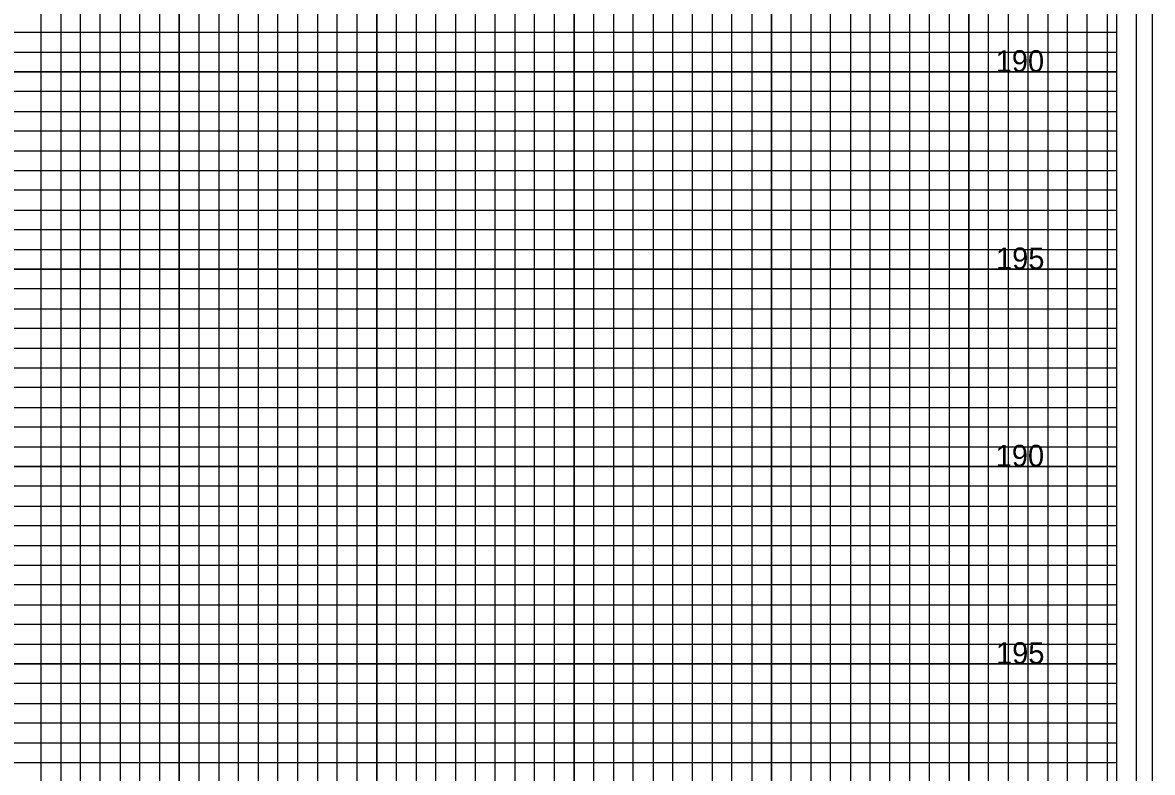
# Model space of a CAD drawing. Extents: x -4 to 103, y -2 to 67.
# Drawn here: x 74.78 to 103.4, y 32.25 to 51.25 of the extents above; entities that cross this region are included whole.
import ezdxf

# ---------------------------------------------------------------- set-up
doc = ezdxf.new("R2010")
doc.units = 0
for name, color, linetype in [('Exist XS Ground Line', 7, 'Continuous'), ('Old_Level_10', 7, 'Continuous'), ('Old_Level_5', 7, 'Continuous'), ('Old_Level_8', 7, 'Continuous'), ('Prop XS Dump Level', 7, 'Continuous'), ('Prop XS Finish Grade', 7, 'Continuous'), ('Prop XS Suitable Common Exc Shape', 7, 'Continuous')]:
    doc.layers.add(name, color=color, linetype=linetype)

msp = doc.modelspace()

# ---------------------------------------------------------------- linework, layer by layer
at = {"layer": 'Exist XS Ground Line'}
msp.add_lwpolyline([(103, 66), (-2.8, 66), (-2.8, -1), (103, -1)], close=True, dxfattribs=at)
at = {"layer": 'Old_Level_10'}
for p, q in [((91.25, 0), (91.25, 63.425)), ((93.75, 0), (93.75, 63.425)), ((96.25, 0), (96.25, 63.425)), ((98.75, 0), (98.75, 63.425)), ((101.25, 0), (101.25, 63.425)), ((76.25, 0), (76.25, 62)), ((78.75, 0), (78.75, 62)), ((81.25, 0), (81.25, 62)), ((83.75, 0), (83.75, 62)), ((86.25, 0), (86.25, 62)), ((88.75, 0), (88.75, 62)), ((0, 50), (102.5, 50)), ((0, 47.5), (102.5, 47.5)), ((0, 45), (102.5, 45)), ((0, 42.5), (102.5, 42.5)), ((0, 40), (102.5, 40)), ((0, 37.5), (102.5, 37.5)), ((0, 35), (102.5, 35)), ((0, 32.5), (102.5, 32.5))]:
    msp.add_line(p, q, dxfattribs=at)
at = {"layer": 'Old_Level_5'}
msp.add_lwpolyline([(103.4, 67.4), (-3.5, 67.4), (-3.5, -2.425), (103.4, -2.425)], close=True, dxfattribs=at)
at = {"layer": 'Old_Level_8'}
for points in [[(91.25, 0), (91.25, 63.425), (93.75, 63.425), (93.75, 0)], [(96.25, 0), (96.25, 63.425), (98.75, 63.425), (98.75, 0)], [(101.25, 0), (101.25, 63.425)], [(76.25, 0), (76.25, 62), (78.75, 62), (78.75, 0)], [(81.25, 0), (81.25, 62), (83.75, 62), (83.75, 0)], [(86.25, 0), (86.25, 62), (88.75, 62), (88.75, 0)], [(0, 47.5), (102.5, 47.5), (102.5, 50), (0, 50)], [(0, 42.5), (102.5, 42.5), (102.5, 45), (0, 45)], [(0, 37.5), (102.5, 37.5), (102.5, 40), (0, 40)], [(0, 32.5), (102.5, 32.5), (102.5, 35), (0, 35)]]:
    msp.add_lwpolyline(points, dxfattribs=at)
at = {"layer": 'Prop XS Dump Level'}
msp.add_lwpolyline([(102.5, 65), (0, 65), (0, 0), (102.5, 0)], close=True, dxfattribs=at)
at = {"layer": 'Prop XS Finish Grade'}
for points in [[(90.25, 0), (90.25, 63.425), (90.75, 63.425), (90.75, 0)], [(91.75, 0), (91.75, 63.425), (92.25, 63.425), (92.25, 0)], [(92.75, 0), (92.75, 63.425), (93.25, 63.425), (93.25, 0)], [(94.25, 0), (94.25, 63.425), (94.75, 63.425), (94.75, 0)], [(95.25, 0), (95.25, 63.425), (95.75, 63.425), (95.75, 0)], [(96.75, 0), (96.75, 63.425), (97.25, 63.425), (97.25, 0)], [(97.75, 0), (97.75, 63.425), (98.25, 63.425), (98.25, 0)], [(99.25, 0), (99.25, 63.425), (99.75, 63.425), (99.75, 0)], [(100.25, 0), (100.25, 63.425)], [(100.25, 63.425), (100.75, 63.425), (100.75, 0), (101.75, 0), (101.75, 63.425), (102.25, 63.425), (102.25, 0)], [(75.25, 0), (75.25, 62), (75.75, 62), (75.75, 0)], [(76.75, 0), (76.75, 62), (77.25, 62), (77.25, 0)], [(77.75, 0), (77.75, 62), (78.25, 62), (78.25, 0)], [(79.25, 0), (79.25, 62), (79.75, 62), (79.75, 0)], [(80.25, 0), (80.25, 62), (80.75, 62), (80.75, 0)], [(81.75, 0), (81.75, 62), (82.25, 62), (82.25, 0)], [(82.75, 0), (82.75, 62), (83.25, 62), (83.25, 0)], [(84.25, 0), (84.25, 62), (84.75, 62), (84.75, 0)], [(85.25, 0), (85.25, 62), (85.75, 62), (85.75, 0)], [(86.75, 0), (86.75, 62), (87.25, 62), (87.25, 0)], [(87.75, 0), (87.75, 62), (88.25, 62), (88.25, 0)], [(89.25, 0), (89.25, 62), (89.75, 62), (89.75, 0)], [(0, 50.5), (102.5, 50.5), (102.5, 51), (0, 51)], [(0, 49), (102.5, 49), (102.5, 49.5), (0, 49.5)], [(0, 48), (102.5, 48), (102.5, 48.5), (0, 48.5)], [(0, 46.5), (102.5, 46.5), (102.5, 47), (0, 47)], [(0, 45.5), (102.5, 45.5), (102.5, 46), (0, 46)], [(0, 44), (102.5, 44), (102.5, 44.5), (0, 44.5)], [(0, 43), (102.5, 43), (102.5, 43.5), (0, 43.5)], [(0, 41.5), (102.5, 41.5), (102.5, 42), (0, 42)], [(0, 40.5), (102.5, 40.5), (102.5, 41), (0, 41)], [(0, 39), (102.5, 39), (102.5, 39.5), (0, 39.5)], [(0, 38), (102.5, 38), (102.5, 38.5), (0, 38.5)], [(0, 36.5), (102.5, 36.5), (102.5, 37), (0, 37)], [(0, 35.5), (102.5, 35.5), (102.5, 36), (0, 36)], [(0, 34), (102.5, 34), (102.5, 34.5), (0, 34.5)], [(0, 33), (102.5, 33), (102.5, 33.5), (0, 33.5)]]:
    msp.add_lwpolyline(points, dxfattribs=at)

# ---------------------------------------------------------------- texts
at = {"layer": 'Prop XS Suitable Common Exc Shape'}
for s, p in [('190', (99.4296, 50)), ('195', (99.4383, 45)), ('190', (99.4296, 40)), ('195', (99.4383, 35))]:
    msp.add_text(s, height=0.55, dxfattribs=at).set_placement(p)

doc.saveas('drawing.dxf')
